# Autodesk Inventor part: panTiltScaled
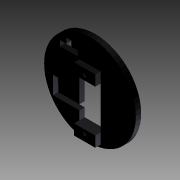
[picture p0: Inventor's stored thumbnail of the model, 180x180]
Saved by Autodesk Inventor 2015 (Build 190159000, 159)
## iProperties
Created: 2015-02
Part Number: panTiltScaled
Material: Generic
Document SubType Name: Modeling
Designer: sungeun
Density: 1 g/cm^3
Appearance: Default
Author: sungeun
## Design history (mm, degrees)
feature "panTilt"
node "MeshFeature1"
body "Solid1"
